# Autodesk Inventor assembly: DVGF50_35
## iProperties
Created: 2010-04
Part Number: DVGF50_35
Document SubType Name: Assembly
Designer: TB
Mass: 793.018 g
Surface Area: 1451.12 cm^2
Volume: 793.018 cm^3
Density: 1 g/cm^3
Description: KM DVGF 50/35 - 100 mm
Slaglengde: 100.000 mm
Author: TB
